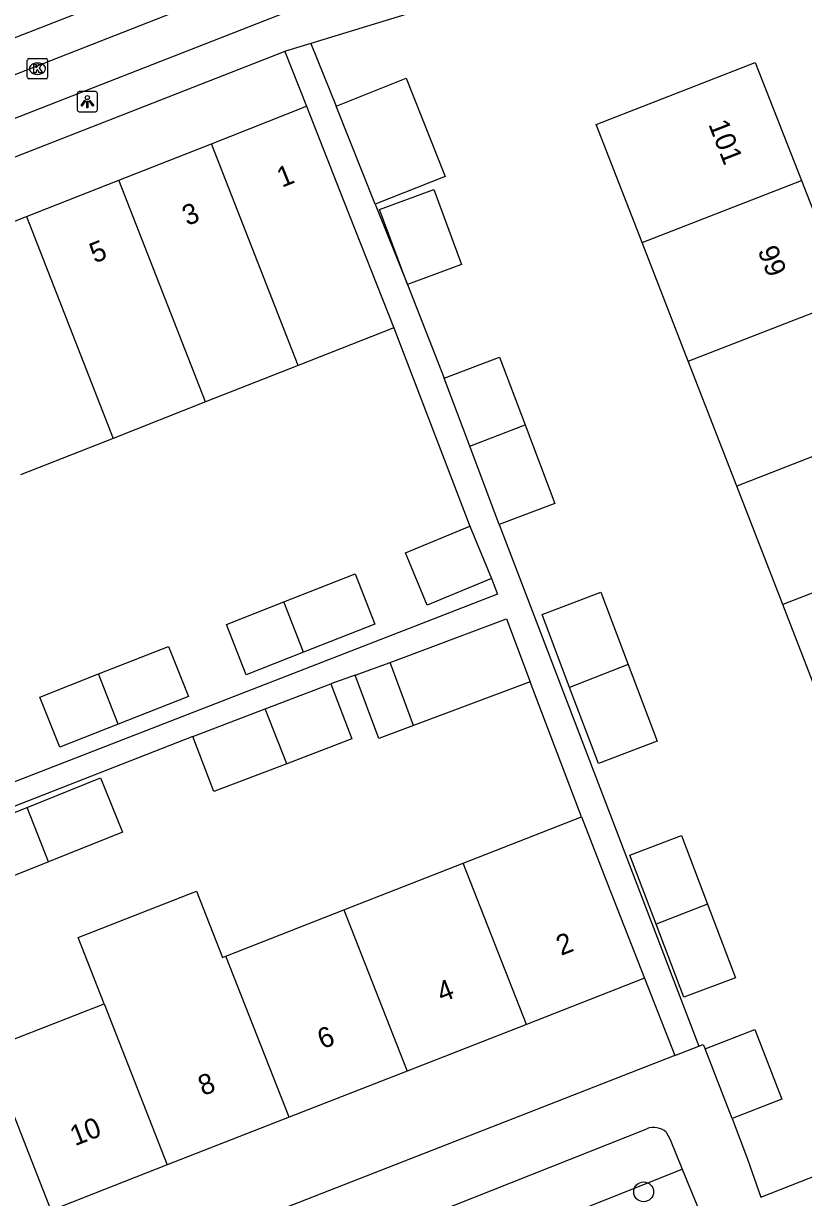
# Model space of a CAD drawing. Extents: x 159689 to 160786, y 387323 to 388339.
# Drawn here: x 160082.4 to 160120.9, y 387907.8 to 387965.8 of the extents above; entities that cross this region are included whole.
import ezdxf

# ---------------------------------------------------------------- set-up
doc = ezdxf.new("R2010")
doc.units = 0
for name, color, linetype in [('IMGEO_Boom', 7, 'Continuous'), ('IMGEO_Groenvoorziening', 7, 'Continuous'), ('IMGEO_Kolk', 7, 'Continuous'), ('IMGEO_Lichtpunt', 7, 'Continuous'), ('IMGEO_Pand', 7, 'Continuous'), ('IMGEO_Pand_nummerreeks', 7, 'Continuous'), ('IMGEO_Rijbaan_lokaal_gesloten', 7, 'Continuous'), ('IMGEO_Voetpad_open', 7, 'Continuous')]:
    doc.layers.add(name, color=color, linetype=linetype)

msp = doc.modelspace()

# ---------------------------------------------------------------- linework, layer by layer
at = {"layer": 'IMGEO_Boom'}
msp.add_circle((160112.964, 387908.102), 0.489, dxfattribs=at)
at = {"layer": 'IMGEO_Groenvoorziening'}
msp.add_lwpolyline([(160103.537, 387904.717), (160114.869, 387909.226)], dxfattribs=at)
at = {"layer": 'IMGEO_Kolk'}
for p, q in [((160082.54, 387963.119), (160082.54, 387963.971)), ((160082.615, 387964.045), (160083.467, 387964.045)), ((160083.028, 387963.825), (160083.053, 387963.825)), ((160083.541, 387963.971), (160083.541, 387963.119)), ((160083.051, 387963.265), (160083.026, 387963.265)), ((160083.467, 387963.045), (160082.615, 387963.045))]:
    msp.add_line(p, q, dxfattribs=at)
for points in [[(160082.54, 387963.119), (160082.54, 387963.971)], [(160082.615, 387964.045), (160083.467, 387964.045)], [(160082.861, 387963.745), (160082.984, 387963.745), (160082.984, 387963.594), (160083.114, 387963.745), (160083.278, 387963.745), (160083.132, 387963.594), (160083.285, 387963.345), (160083.133, 387963.345), (160083.048, 387963.509), (160082.984, 387963.442), (160082.984, 387963.345), (160082.861, 387963.345), (160082.861, 387963.745)], [(160083.541, 387963.971), (160083.541, 387963.119)], [(160083.467, 387963.045), (160082.615, 387963.045)]]:
    msp.add_lwpolyline(points, dxfattribs=at)
for centre, start, end in [((160082.617, 387963.969), 91.55205, 178.44795), ((160082.617, 387963.969), 91.55205, 178.44795), ((160083.465, 387963.969), 1.55205, 88.44795), ((160083.465, 387963.969), 1.55205, 88.44795), ((160082.617, 387963.121), 181.55205, 268.44795), ((160082.617, 387963.121), 181.55205, 268.44795), ((160083.465, 387963.121), 271.55205, 358.44795), ((160083.465, 387963.121), 271.55205, 358.44795)]:
    msp.add_arc(centre, 0.0765, start, end, dxfattribs=at)
for centre, major_axis, ratio, start_param, end_param in [((160083.027, 387963.545), (-0.387, 0.002), 0.722429, 4.712389, 7.853982), ((160083.052, 387963.545), (-0.39, 0.002), 0.717154, 1.570796, 4.712389)]:
    msp.add_ellipse(centre, major_axis=major_axis, ratio=ratio, start_param=start_param, end_param=end_param, dxfattribs=at)
at = {"layer": 'IMGEO_Lichtpunt'}
for p, q in [((160085.005, 387962.319), (160085.005, 387961.512)), ((160085.005, 387962.319), (160085.005, 387961.512)), ((160085.907, 387962.414), (160085.099, 387962.414)), ((160085.907, 387962.414), (160085.099, 387962.414)), ((160086.001, 387961.512), (160086.001, 387962.319)), ((160086.001, 387961.512), (160086.001, 387962.319)), ((160085.099, 387961.418), (160085.907, 387961.418)), ((160085.099, 387961.418), (160085.907, 387961.418))]:
    msp.add_line(p, q, dxfattribs=at)
for points in [[(160085.379, 387961.983), (160085.418, 387961.955), (160085.23, 387961.693), (160085.192, 387961.72), (160085.379, 387961.983)], [(160085.481, 387961.935), (160085.528, 387961.935), (160085.528, 387961.613), (160085.481, 387961.613), (160085.481, 387961.935)], [(160085.591, 387961.955), (160085.629, 387961.982), (160085.816, 387961.72), (160085.777, 387961.692), (160085.591, 387961.955)]]:
    msp.add_lwpolyline(points, dxfattribs=at)
msp.add_circle((160085.504, 387962.117), 0.0994, dxfattribs=at)
for centre, start, end in [((160085.099, 387962.319), 90, 180), ((160085.099, 387962.319), 90, 180), ((160085.907, 387962.319), 0, 90), ((160085.907, 387962.319), 0, 90), ((160085.099, 387961.512), 180, 270), ((160085.099, 387961.512), 180, 270), ((160085.907, 387961.512), 270, 0), ((160085.907, 387961.512), 270, 360)]:
    msp.add_arc(centre, 0.0946, start, end, dxfattribs=at)
at = {"layer": 'IMGEO_Pand'}
for points in [[(160112.885, 387954.968), (160110.623, 387960.789), (160118.478, 387963.856), (160120.754, 387958.026)], [(160097.787, 387961.694), (160101.244, 387963.071), (160103.173, 387958.229), (160099.716, 387956.852)], [(160091.626, 387959.841), (160096.317, 387961.689)], [(160096.317, 387961.689), (160098.149, 387957.037), (160100.625, 387950.752)], [(160099.716, 387956.852), (160097.787, 387961.694)], [(160087.059, 387958.042), (160091.626, 387959.841)], [(160095.91, 387948.895), (160091.626, 387959.841)], [(160082.492, 387956.243), (160087.059, 387958.042)], [(160091.343, 387947.096), (160087.059, 387958.042)], [(160112.885, 387954.968), (160120.754, 387958.026)], [(160120.754, 387958.026), (160123.043, 387952.16)], [(160101.306, 387952.888), (160099.931, 387956.594), (160102.599, 387957.584), (160103.974, 387953.878), (160101.306, 387952.888)], [(160078.124, 387953.933), (160081.112, 387955.11), (160080.911, 387955.62), (160082.492, 387956.243)], [(160082.492, 387956.243), (160086.776, 387945.297)], [(160115.165, 387949.099), (160112.885, 387954.968)], [(160115.165, 387949.099), (160123.043, 387952.16)], [(160100.625, 387950.752), (160095.91, 387948.895)], [(160103.114, 387948.275), (160105.857, 387949.308), (160107.114, 387945.971)], [(160095.91, 387948.895), (160091.343, 387947.096)], [(160117.557, 387942.943), (160115.165, 387949.099)], [(160104.381, 387944.909), (160103.114, 387948.275)], [(160091.343, 387947.096), (160086.776, 387945.297)], [(160104.381, 387944.909), (160107.114, 387945.971)], [(160107.114, 387945.971), (160108.578, 387942.084), (160105.834, 387941.051)], [(160125.445, 387946.008), (160117.557, 387942.943)], [(160086.776, 387945.297), (160082.208, 387943.497)], [(160105.834, 387941.051), (160104.381, 387944.909)], [(160119.83, 387937.093), (160117.557, 387942.943)], [(160105.454, 387938.379), (160102.28, 387937.066), (160101.212, 387939.647), (160104.386, 387940.96)], [(160104.386, 387940.96), (160105.454, 387938.379)], [(160127.727, 387940.161), (160119.83, 387937.093)], [(160095.208, 387937.221), (160098.717, 387938.604), (160099.695, 387936.123), (160096.18, 387934.738)], [(160109.309, 387933.006), (160107.949, 387936.599), (160110.847, 387937.697), (160112.199, 387934.128)], [(160096.18, 387934.738), (160093.347, 387933.621), (160092.369, 387936.102), (160095.208, 387937.221)], [(160096.18, 387934.738), (160095.208, 387937.221)], [(160122.096, 387931.263), (160119.83, 387937.093)], [(160100.446, 387934.229), (160106.193, 387936.384), (160107.355, 387933.284)], [(160086.055, 387933.666), (160089.511, 387935.029), (160090.489, 387932.548), (160087.027, 387931.183)], [(160098.716, 387933.609), (160100.446, 387934.229)], [(160101.609, 387931.13), (160100.446, 387934.229)], [(160112.199, 387934.128), (160113.63, 387930.348), (160110.732, 387929.25), (160109.309, 387933.006)], [(160112.199, 387934.128), (160109.309, 387933.006)], [(160087.027, 387931.183), (160084.141, 387930.046), (160083.163, 387932.527), (160086.055, 387933.666)], [(160087.027, 387931.183), (160086.055, 387933.666)], [(160101.609, 387931.13), (160099.887, 387930.484), (160098.716, 387933.609)], [(160094.288, 387931.947), (160097.53, 387933.184)], [(160097.53, 387933.184), (160098.567, 387930.463), (160095.35, 387929.234)], [(160107.355, 387933.284), (160101.609, 387931.13)], [(160090.703, 387930.58), (160094.288, 387931.947)], [(160095.35, 387929.234), (160094.288, 387931.947)], [(160095.35, 387929.234), (160091.741, 387927.857), (160090.703, 387930.58)], [(160082.534, 387927.082), (160086.159, 387928.536), (160087.235, 387925.851), (160083.588, 387924.389)], [(160083.588, 387924.389), (160079.923, 387922.92), (160078.847, 387925.604), (160082.534, 387927.082)], [(160083.588, 387924.389), (160082.534, 387927.082)], [(160104.059, 387924.33), (160109.889, 387926.613)], [(160109.889, 387926.613), (160111.186, 387923.31), (160113.014, 387918.655)], [(160113.579, 387921.309), (160112.285, 387924.724), (160114.834, 387925.69), (160116.119, 387922.296)], [(160098.172, 387922.026), (160104.059, 387924.33)], [(160107.176, 387916.369), (160104.059, 387924.33)], [(160086.329, 387917.389), (160085.049, 387920.659), (160090.892, 387922.947), (160092.173, 387919.677), (160092.341, 387919.743)], [(160092.341, 387919.743), (160098.172, 387922.026)], [(160098.172, 387922.026), (160101.289, 387914.065)], [(160116.119, 387922.296), (160117.493, 387918.669), (160114.944, 387917.704), (160113.579, 387921.309)], [(160116.119, 387922.296), (160113.579, 387921.309)], [(160095.458, 387911.782), (160092.341, 387919.743)], [(160113.014, 387918.655), (160107.176, 387916.369)], [(160080.594, 387915.144), (160086.329, 387917.389)], [(160086.329, 387917.389), (160089.446, 387909.428)], [(160107.176, 387916.369), (160101.289, 387914.065)], [(160116.002, 387915.162), (160118.459, 387916.115), (160119.792, 387912.679), (160117.335, 387911.726)], [(160083.711, 387907.182), (160080.594, 387915.144)], [(160117.335, 387911.726), (160116.002, 387915.162)], [(160101.289, 387914.065), (160095.458, 387911.782)], [(160095.458, 387911.782), (160089.446, 387909.428)], [(160089.446, 387909.428), (160083.711, 387907.182)]]:
    msp.add_lwpolyline(points, dxfattribs=at)
at = {"layer": 'IMGEO_Rijbaan_lokaal_gesloten'}
for points in [[(160048.287, 387951.938), (160068.231, 387959.752), (160084.184, 387965.957), (160115.127, 387978.084)], [(160094.863, 387968.326), (160078.123, 387961.765)]]:
    msp.add_lwpolyline(points, dxfattribs=at)
at = {"layer": 'IMGEO_Voetpad_open'}
for points in [[(160117.173, 387970.931), (160116.204, 387970.698), (160110.655, 387969.121), (160096.541, 387964.792)], [(160078.84, 387959.903), (160095.696, 387966.485), (160094.863, 387968.326)], [(160095.257, 387964.396), (160062.822, 387951.706), (160046.468, 387945.307)], [(160096.541, 387964.792), (160095.279, 387964.405), (160095.257, 387964.396)], [(160095.257, 387964.396), (160096.317, 387961.689)], [(160096.541, 387964.792), (160097.787, 387961.694)], [(160099.716, 387956.852), (160101.306, 387952.888)], [(160101.306, 387952.888), (160103.114, 387948.275)], [(160100.625, 387950.752), (160104.386, 387940.96)], [(160105.834, 387941.051), (160115.683, 387915.296)], [(160105.454, 387938.379), (160105.753, 387937.608), (160056.91, 387918.63), (160053.456, 387927.503)], [(160098.716, 387933.609), (160097.53, 387933.184)], [(160109.889, 387926.613), (160107.355, 387933.284)], [(160090.703, 387930.58), (160052.947, 387915.796), (160056.844, 387905.845)], [(160113.014, 387918.655), (160114.506, 387914.836)], [(160117.335, 387911.726), (160118.086, 387909.722), (160118.757, 387907.847), (160120.676, 387908.594), (160140.13, 387916.234)], [(160114.506, 387914.836), (160115.683, 387915.296)], [(160115.683, 387915.296), (160115.897, 387915.38), (160116.002, 387915.162)], [(160114.506, 387914.836), (160061.446, 387894.107)], [(160102.621, 387907.043), (160113.119, 387911.22)], [(160114.072, 387911.049), (160114.271, 387910.688), (160114.869, 387909.226)], [(160114.869, 387909.226), (160115.857, 387906.811)]]:
    msp.add_lwpolyline(points, dxfattribs=at)
msp.add_arc((160113.455, 387910.35), 0.932, 48.54273, 111.11222, dxfattribs=at)

# ---------------------------------------------------------------- texts
at = {"layer": 'IMGEO_Pand_nummerreeks'}
for s, rotation, p in [('101', 291.32145, (160116.148, 387960.803)), ('1', 22.01889, (160095.111, 387957.663)), ('3', 22.01889, (160090.435, 387955.771)), ('5', 22.01889, (160085.863, 387953.923)), ('99', 291.32145, (160118.58, 387954.573)), ('2', 21.38117, (160108.89, 387919.747)), ('4', 21.38117, (160102.998, 387917.44)), ('6', 21.38117, (160097.104, 387915.133)), ('8', 21.38278, (160091.214, 387912.826)), ('10', 21.38117, (160084.891, 387910.35))]:
    msp.add_text(s, height=1, rotation=rotation, dxfattribs=at).set_placement(p)

doc.saveas('drawing.dxf')
